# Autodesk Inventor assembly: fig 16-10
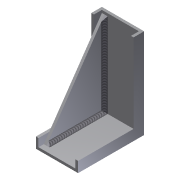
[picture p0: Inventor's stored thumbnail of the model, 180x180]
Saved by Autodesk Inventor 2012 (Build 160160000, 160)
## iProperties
Shininess: 64.0
Length Units: 11269
Angle Units: 11279
Time Units: 11290
Mass Units: 11283
Length Display Precision: 3
Angle Display Precision: 2
Compacted: True
Created: 2003-01
Part Number: fig 16-10
Document SubType Name: Weldment
Designer: Owner
Density: 0.0
Volumn: 0.0
Area: 0.0
PropertySet Name: Model Information
Control State: 0
Master: False
Checked Out: False
Author: Owner
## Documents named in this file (3)
- C:\Users\CadCim\Documents\SAILESH\inventor-2011-fact-prt\c16-inv-2011-prt\c16_inv_2012_prt\fig 16-10\fig 16-10.iam
- C:\Users\CadCim\Documents\SAILESH\inventor-2011-fact-prt\c16-inv-2011-prt\figure-16-10\Bracket-1.ipt
- C:\Users\CadCim\Documents\SAILESH\inventor-2011-fact-prt\c16-inv-2011-prt\figure-16-10\Bracket-plate.ipt
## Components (2 placed, 2 different names)
1. Bracket-1:1 — Mate:1, Mate:2
2. Bracket-plate:1 — Mate:1, Mate:2
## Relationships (2: Mate 2)
- Mate:1: Bracket-1:1 ↔ Bracket-plate:1
- Mate:2: Bracket-1:1 ↔ Bracket-plate:1
